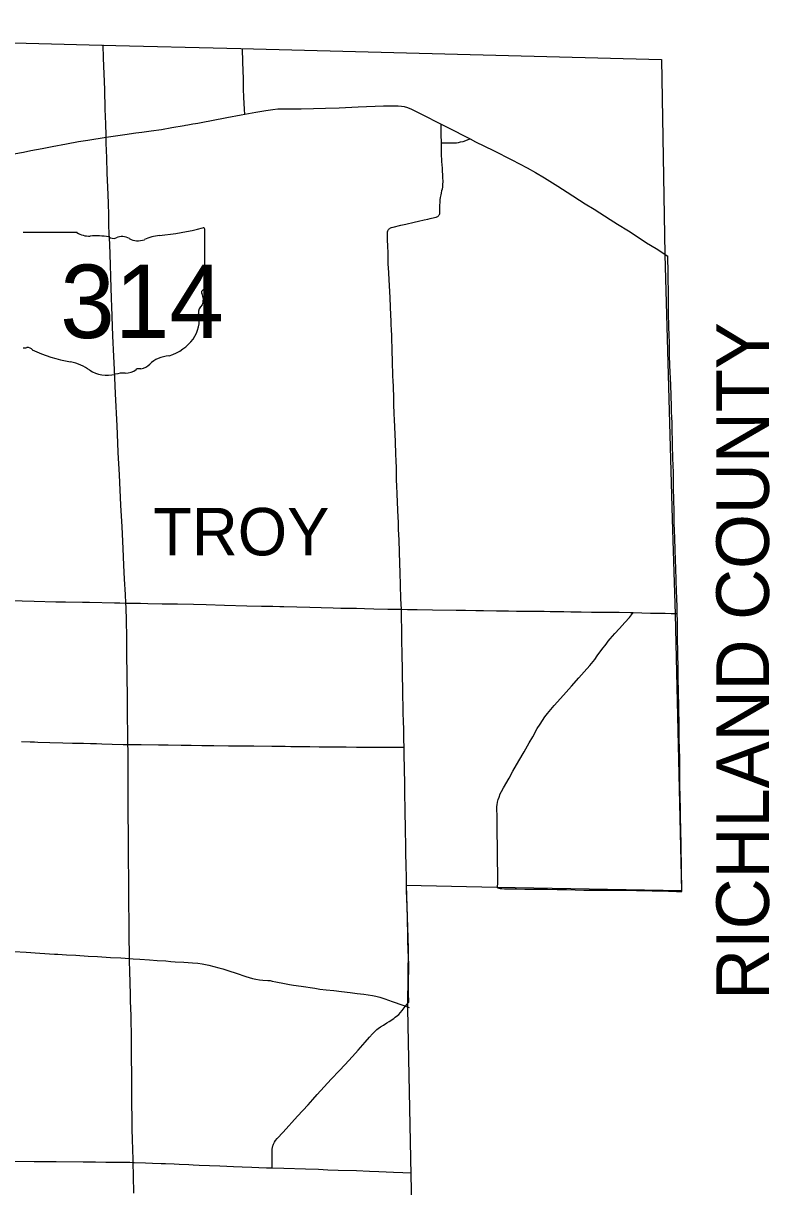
# Model space of a CAD drawing. Extents: x 9078 to 9739, y 4248 to 4966.
# Drawn here: x 9605 to 9675.8, y 4827.9 to 4938.2 of the extents above; entities that cross this region are included whole.
import ezdxf

# ---------------------------------------------------------------- set-up
doc = ezdxf.new("R2010")
doc.units = 0
for name, color, linetype in [('GM_X_Adjacent_County_Text', 7, 'Continuous'), ('GM_X_County', 7, 'Continuous'), ('GM_X_County_Road', 7, 'Continuous'), ('GM_X_State_Route', 7, 'Continuous'), ('GM_X_State_Shield', 7, 'Continuous'), ('GM_X_Township_Road', 7, 'Continuous'), ('GM_X_Township_Text', 7, 'Continuous')]:
    doc.layers.add(name, color=color, linetype=linetype)

msp = doc.modelspace()

# ---------------------------------------------------------------- linework, layer by layer
at = {"layer": 'GM_X_County'}
msp.add_lwpolyline([(9527.58, 4938.18), (9534.01, 4938.03), (9544.57, 4937.79), (9580.15, 4937.8), (9580.15, 4936.95), (9612.46, 4936.11), (9625.64, 4935.77), (9665.53, 4934.74), (9665.86, 4916.26), (9666.54, 4891.17), (9666.82, 4882.14), (9667.42, 4855.9), (9649.93, 4856.23), (9641.33, 4856.41), (9641.51, 4850.43), (9641.44, 4845.14), (9641.45, 4844.73), (9641.78, 4828.99), (9642.12, 4813.07)], dxfattribs=at)
at = {"layer": 'GM_X_County_Road'}
for points in [[(9597.99, 4883.64), (9598.12, 4883.64), (9598.92, 4883.61), (9599.5, 4883.58), (9600.48, 4883.55), (9602.12, 4883.51), (9603.43, 4883.47), (9604.91, 4883.42), (9606.05, 4883.39), (9608.1, 4883.33), (9609.01, 4883.31), (9610.64, 4883.29), (9611.3, 4883.28), (9613.67, 4883.22), (9614.16, 4883.21), (9614.73, 4883.2)], [(9614.73, 4883.2), (9615.49, 4883.18), (9616.13, 4883.18), (9616.82, 4883.17), (9618.18, 4883.14), (9619.65, 4883.12), (9621.14, 4883.09), (9622.36, 4883.05), (9624.08, 4883.01), (9626.21, 4882.94), (9627.6, 4882.91), (9628.67, 4882.89), (9629.33, 4882.87), (9629.73, 4882.86), (9630.96, 4882.83), (9632.19, 4882.8), (9633.26, 4882.77), (9634.41, 4882.75), (9635.14, 4882.73), (9635.88, 4882.72), (9636.62, 4882.7), (9637.36, 4882.68), (9638.26, 4882.66), (9639.57, 4882.63), (9640.8, 4882.61), (9640.87, 4882.61)], [(9640.87, 4882.61), (9641.45, 4882.59), (9642.36, 4882.58), (9643.83, 4882.56), (9646.05, 4882.53), (9646.95, 4882.52), (9647.93, 4882.5), (9648.67, 4882.49), (9649.9, 4882.47), (9651.04, 4882.45), (9651.78, 4882.44), (9652.76, 4882.43), (9653.17, 4882.43), (9653.58, 4882.43), (9654.4, 4882.42), (9654.97, 4882.41), (9655.63, 4882.41), (9656.28, 4882.39), (9656.94, 4882.38), (9657.92, 4882.37), (9658.91, 4882.35), (9659.48, 4882.34), (9660.55, 4882.34), (9661.53, 4882.32), (9662.6, 4882.29), (9662.86, 4882.29)], [(9662.86, 4882.29), (9663.67, 4882.26), (9664.48, 4882.25), (9665.22, 4882.24), (9665.88, 4882.23), (9666.45, 4882.22), (9666.94, 4882.22), (9667.03, 4882.21)], [(9604.84, 4870.07), (9605.66, 4870.04), (9606.07, 4870.03), (9606.39, 4870.02), (9607.54, 4869.98), (9608.77, 4869.95), (9609.67, 4869.92), (9610.73, 4869.9), (9611.39, 4869.88), (9611.96, 4869.87), (9612.45, 4869.85), (9613.44, 4869.82), (9614.49, 4869.79), (9614.94, 4869.79)], [(9603.54, 4830.29), (9606.03, 4830.26), (9608.14, 4830.25), (9610.7, 4830.22), (9611.85, 4830.2), (9612.84, 4830.19), (9613.66, 4830.19), (9614.64, 4830.19), (9615.13, 4830.17), (9615.42, 4830.15)], [(9615.42, 4830.15), (9615.54, 4830.15), (9616.61, 4830.12), (9617.26, 4830.09), (9618.08, 4830.06), (9618.49, 4830.05), (9619.31, 4830.01), (9619.8, 4829.98), (9620.7, 4829.95), (9621.11, 4829.93), (9621.69, 4829.91), (9622.67, 4829.87), (9623.65, 4829.83), (9624.31, 4829.81), (9624.96, 4829.78), (9625.78, 4829.75), (9626.69, 4829.71), (9627.34, 4829.69), (9628.08, 4829.66), (9628.63, 4829.65)], [(9628.63, 4829.65), (9628.65, 4829.65), (9629.72, 4829.62), (9631.77, 4829.56), (9633, 4829.51), (9633.9, 4829.47), (9634.88, 4829.43), (9636.6, 4829.38), (9637.83, 4829.33), (9638.72, 4829.29), (9640.12, 4829.23), (9641.01, 4829.19), (9641.8, 4829.17)]]:
    msp.add_lwpolyline(points, dxfattribs=at)
at = {"layer": 'GM_X_State_Route'}
for points in [[(9615.49, 4827.25), (9615.45, 4828.89), (9615.42, 4830.15), (9615.42, 4830.44), (9615.38, 4832.33), (9615.35, 4833.31), (9615.32, 4836.76), (9615.31, 4837.74), (9615.31, 4838.15), (9615.31, 4838.32), (9615.3, 4838.97), (9615.29, 4839.63), (9615.28, 4840.45), (9615.28, 4841.6), (9615.27, 4842.01), (9615.26, 4842.66), (9615.25, 4843.24), (9615.23, 4844.22), (9615.21, 4844.63), (9615.19, 4845.62), (9615.17, 4846.19), (9615.15, 4847.09), (9615.12, 4848.4), (9615.1, 4849.14), (9615.09, 4849.5), (9615.07, 4850.21), (9615.06, 4851.19), (9615.04, 4852.34), (9615.04, 4852.92), (9615.04, 4853.57), (9615.03, 4854.15), (9615.03, 4855.29), (9615.02, 4855.87), (9615.01, 4856.2), (9615.01, 4856.52), (9615.01, 4857.26), (9615.01, 4857.67), (9615, 4858.24), (9614.99, 4858.9), (9614.98, 4859.64), (9614.99, 4860.13), (9614.99, 4861.11), (9614.97, 4863.33), (9614.97, 4864.07), (9614.97, 4864.89), (9614.97, 4865.63), (9614.96, 4866.28), (9614.96, 4866.94), (9614.96, 4867.6), (9614.96, 4868.17), (9614.95, 4868.66), (9614.95, 4869.32), (9614.94, 4869.73), (9614.94, 4869.79), (9614.93, 4870.55), (9614.92, 4871.37), (9614.91, 4871.94), (9614.9, 4873.26), (9614.88, 4874.4), (9614.86, 4876.13), (9614.85, 4876.87), (9614.83, 4877.85), (9614.82, 4878.67), (9614.82, 4879.41), (9614.82, 4879.98), (9614.79, 4881.54), (9614.76, 4882.77), (9614.73, 4883.2), (9614.7, 4884), (9614.62, 4885.48), (9614.56, 4886.78), (9614.48, 4888.38), (9614.38, 4890.43), (9614.27, 4892.48), (9614.13, 4895.35), (9614.02, 4897.48), (9613.97, 4898.38), (9613.91, 4900.02), (9613.77, 4903.05), (9613.65, 4905.35), (9613.59, 4906.58), (9613.51, 4908.54), (9613.48, 4909.45), (9613.4, 4911.33), (9613.37, 4912.07), (9613.31, 4914.12), (9613.27, 4915.27), (9613.21, 4917.23), (9613.16, 4918.29), (9613.14, 4918.97), (9613.12, 4919.94), (9613.08, 4921.16), (9613.02, 4922.65), (9612.98, 4923.95), (9612.92, 4925.43), (9612.88, 4926.81), (9612.87, 4927.37), (9612.86, 4927.55), (9612.84, 4928.63), (9612.79, 4930.02), (9612.75, 4931.9), (9612.63, 4934.86), (9612.58, 4936.12)], [(9604.13, 4925.81), (9605.02, 4925.96), (9605.74, 4926.1), (9606.79, 4926.3), (9607.76, 4926.48), (9609.12, 4926.74), (9610.25, 4926.96), (9611.14, 4927.1), (9612.87, 4927.37), (9613.09, 4927.41), (9614.63, 4927.63), (9615.68, 4927.78), (9616.25, 4927.85), (9617.15, 4927.97), (9618.12, 4928.12), (9619.09, 4928.3), (9620.27, 4928.49), (9620.41, 4928.51), (9620.62, 4928.55), (9621.1, 4928.63), (9621.34, 4928.68), (9621.57, 4928.72), (9622.05, 4928.81), (9622.86, 4928.97), (9624.31, 4929.23), (9625.68, 4929.5), (9626.02, 4929.56), (9627.05, 4929.75), (9628.02, 4929.92), (9628.67, 4930.01), (9629.16, 4930.05), (9629.65, 4930.07), (9631.38, 4930.06), (9632.52, 4930.09), (9633.67, 4930.13), (9634.98, 4930.17), (9636.78, 4930.24), (9639.16, 4930.34), (9639.98, 4930.36), (9640.56, 4930.36), (9640.89, 4930.33), (9641.13, 4930.28), (9641.45, 4930.19), (9641.83, 4930.03), (9642.78, 4929.56), (9644.65, 4928.6), (9645.7, 4928.07), (9646.87, 4927.47), (9647.4, 4927.21), (9647.9, 4926.95), (9649.59, 4926.11), (9651.34, 4925.22), (9652.8, 4924.47), (9653.59, 4924.03), (9654.44, 4923.53), (9655.69, 4922.74), (9656.59, 4922.17), (9658.31, 4921.07), (9659.14, 4920.54), (9660.67, 4919.58), (9661.36, 4919.14), (9662.4, 4918.48), (9663.43, 4917.82), (9664.12, 4917.37), (9665.03, 4916.81), (9666.15, 4916.09)]]:
    msp.add_lwpolyline(points, dxfattribs=at)
at = {"layer": 'GM_X_State_Shield'}
for p, q in [((9610.11, 4918.34), (9605.01, 4918.34)), ((9622.24, 4913.07), (9622.24, 4918.6)), ((9622.24, 4913.07), (9622.24, 4913.07))]:
    msp.add_line(p, q, dxfattribs=at)
for centre, major_axis, start_param, end_param in [((9611.32, 4919.56), (1.96, 0), 4.042523, 4.731795), ((9616.04, 4932.74), (18.45, 0), 4.814394, 5.042369), ((9622.05, 4918.62), (0.194, 0), 6.141152, 7.989035), ((9611.97, 4912.4), (7.02, 0), 1.404758, 1.657858), ((9613.56, 4918.23), (0.564, 0), 3.836095, 5.185415), ((9614.39, 4917.01), (1.17, 0), 0.950623, 2.079405), ((9615.9, 4918.68), (1.41, 0), 4.081561, 5.145723), ((9618.4, 4915.11), (3.71, 0), 1.699011, 2.107814), ((9622.2, 4912.66), (0.3, 0), 1.883978, 3.671073), ((9622.03, 4913.05), (0.207, 0), 5.05454, 6.418171), ((9620.29, 4911.97), (1.8, 0), 5.934695, 6.695948), ((9617.08, 4910.05), (4.62, 0), 5.101752, 6.440018), ((9622.94, 4910.76), (1.31, 0), 2.387724, 3.262537), ((9605.07, 4908.64), (1.55, 0), 4.665946, 4.897461), ((9605.39, 4906.98), (0.56, 0), 0.519207, 1.627899), ((9612.45, 4916.47), (13.33, 0), 4.195997, 4.488961), ((9619.02, 4904.62), (2.53, 0), 1.647645, 2.488434), ((9608.48, 4902.84), (4.17, 0), 0.823519, 1.323587), ((9612.99, 4906.92), (2.65, 0), 4.026481, 4.996735), ((9614.71, 4906.13), (1.41, 0), 4.691044, 5.507374), ((9615.99, 4905.11), (0.397, 0), 1.147584, 2.315152), ((9615.82, 4906.56), (1.49, 0), 4.937069, 5.64225), ((9614.52, 4903.27), (2.17, 0), 1.495662, 1.94098)]:
    msp.add_ellipse(centre, major_axis=major_axis, ratio=0.8, start_param=start_param, end_param=end_param, dxfattribs=at)
at = {"layer": 'GM_X_Township_Road'}
for points in [[(9626.02, 4929.56), (9625.99, 4930), (9625.93, 4931.18), (9625.91, 4931.93), (9625.88, 4932.92), (9625.84, 4934.48), (9625.8, 4935.78)], [(9644.66, 4926.84), (9644.64, 4927.62), (9644.65, 4928.51), (9644.65, 4928.6)], [(9644.66, 4926.84), (9645.09, 4926.83), (9645.36, 4926.83), (9645.6, 4926.83), (9645.85, 4926.84), (9646.09, 4926.85), (9646.27, 4926.87), (9646.49, 4926.92), (9646.73, 4926.98), (9647.31, 4927.18), (9647.4, 4927.21)], [(9639.62, 4915.94), (9639.61, 4916.19), (9639.61, 4916.53), (9639.59, 4916.92), (9639.58, 4917.18), (9639.56, 4917.5), (9639.55, 4917.75), (9639.54, 4917.99), (9639.54, 4918.15), (9639.54, 4918.23), (9639.55, 4918.32), (9639.56, 4918.39), (9639.58, 4918.48), (9639.61, 4918.56), (9639.66, 4918.62), (9639.72, 4918.68), (9639.78, 4918.73), (9639.85, 4918.77), (9639.93, 4918.8), (9640.09, 4918.85), (9640.81, 4919.02), (9641.29, 4919.14), (9642.08, 4919.32), (9642.48, 4919.42), (9643.04, 4919.54), (9643.37, 4919.61), (9643.61, 4919.67), (9644.01, 4919.75), (9644.17, 4919.79), (9644.24, 4919.82), (9644.31, 4919.86), (9644.38, 4919.91), (9644.43, 4919.97), (9644.48, 4920.04), (9644.51, 4920.11), (9644.53, 4920.19), (9644.53, 4920.27), (9644.53, 4920.52), (9644.53, 4920.93), (9644.54, 4921.18), (9644.55, 4921.42), (9644.58, 4921.67), (9644.63, 4921.91), (9644.66, 4922.07), (9644.72, 4922.31), (9644.76, 4922.47), (9644.79, 4922.63), (9644.81, 4922.87), (9644.82, 4923.2), (9644.81, 4923.53), (9644.76, 4924.43), (9644.72, 4925.08), (9644.68, 4925.82), (9644.67, 4926.07), (9644.66, 4926.84)], [(9640.42, 4894.82), (9640.4, 4895.53), (9640.39, 4895.98), (9640.37, 4896.72), (9640.35, 4897.29), (9640.3, 4898.52), (9640.22, 4900.57), (9640.19, 4901.15), (9640.16, 4902.05), (9640.16, 4902.29), (9640.15, 4902.53), (9640.14, 4902.69), (9640.11, 4903.67), (9640.08, 4904.33), (9640.07, 4904.66), (9640.05, 4905.15), (9640.03, 4905.72), (9640.02, 4906.13), (9639.99, 4907.12), (9639.95, 4908.43), (9639.92, 4909.25), (9639.91, 4909.49), (9639.89, 4909.9), (9639.84, 4911.21), (9639.8, 4912.2), (9639.77, 4912.69), (9639.74, 4913.34), (9639.72, 4913.83), (9639.67, 4914.56), (9639.66, 4914.97), (9639.63, 4915.37), (9639.62, 4915.87), (9639.62, 4915.94)], [(9666.74, 4891.31), (9666.73, 4891.43), (9666.73, 4891.92), (9666.72, 4892.98), (9666.68, 4894.13), (9666.67, 4894.63), (9666.66, 4895.53), (9666.63, 4896.34), (9666.61, 4896.83), (9666.6, 4897.32), (9666.58, 4897.81), (9666.57, 4898.22), (9666.57, 4898.79), (9666.56, 4899.37), (9666.55, 4899.94), (9666.54, 4900.19), (9666.51, 4900.93), (9666.5, 4901.25), (9666.49, 4901.5), (9666.47, 4901.83), (9666.44, 4902.89), (9666.41, 4903.87), (9666.39, 4904.53), (9666.37, 4905.1), (9666.34, 4905.76), (9666.31, 4906.66), (9666.29, 4907.23), (9666.28, 4907.8), (9666.25, 4908.71), (9666.23, 4909.29), (9666.22, 4909.77), (9666.21, 4910.34), (9666.2, 4911.08), (9666.2, 4912.38), (9666.19, 4912.95), (9666.18, 4913.73), (9666.17, 4914.47), (9666.15, 4916.09)], [(9640.87, 4882.61), (9640.83, 4883.61), (9640.79, 4884.92), (9640.74, 4886.07), (9640.72, 4886.97), (9640.69, 4888.03), (9640.65, 4889.18), (9640.61, 4890.16), (9640.58, 4890.9), (9640.56, 4891.31), (9640.54, 4892.05), (9640.47, 4893.52), (9640.44, 4894.34), (9640.42, 4894.82)], [(9667.03, 4882.21), (9667.03, 4882.42), (9667.01, 4883.07), (9667, 4883.4), (9666.99, 4883.73), (9666.97, 4884.3), (9666.94, 4885.44), (9666.9, 4886.43), (9666.87, 4887.33), (9666.83, 4888.23), (9666.79, 4889.38), (9666.75, 4890.77), (9666.74, 4891.31)], [(9641.13, 4869.52), (9641.11, 4870.25), (9641.11, 4871.07), (9641.07, 4872.13), (9641.05, 4872.62), (9641.04, 4873.28), (9641.02, 4874.51), (9640.98, 4876.88), (9640.95, 4878.36), (9640.92, 4879.67), (9640.91, 4880.25), (9640.9, 4880.98), (9640.89, 4881.56), (9640.88, 4882.46), (9640.87, 4882.61)], [(9649.97, 4856.19), (9649.98, 4856.33), (9650, 4856.62), (9650.01, 4857.03), (9650.01, 4857.69), (9649.99, 4858.67), (9649.98, 4859.41), (9649.97, 4860.39), (9649.96, 4861.13), (9649.94, 4862.03), (9649.94, 4863.02), (9649.93, 4863.67), (9649.93, 4863.92), (9649.95, 4864.08), (9649.99, 4864.32), (9650.05, 4864.56), (9650.13, 4864.8), (9650.25, 4865.1), (9650.36, 4865.32), (9650.55, 4865.67), (9651.08, 4866.61), (9651.44, 4867.25), (9652.02, 4868.24), (9652.51, 4869.09), (9652.99, 4869.95), (9653.32, 4870.52), (9653.76, 4871.31), (9654.02, 4871.73), (9654.24, 4872.07), (9654.48, 4872.4), (9654.74, 4872.72), (9655.37, 4873.48), (9656.23, 4874.47), (9657, 4875.32), (9657.71, 4876.12), (9658.2, 4876.67), (9658.73, 4877.29), (9659.2, 4877.86), (9659.45, 4878.18), (9659.89, 4878.78), (9660.28, 4879.3), (9660.48, 4879.57), (9660.68, 4879.82), (9661.12, 4880.31), (9661.56, 4880.79), (9662.05, 4881.34), (9662.49, 4881.83), (9662.7, 4882.09), (9662.86, 4882.29)], [(9667.47, 4855.85), (9667.46, 4856.02), (9667.42, 4857.88), (9667.39, 4860.34), (9667.34, 4862.97), (9667.33, 4863.79), (9667.31, 4864.69), (9667.29, 4866.09), (9667.28, 4866.74), (9667.27, 4867.65), (9667.26, 4868.63), (9667.24, 4869.21), (9667.22, 4870.44), (9667.2, 4871.58), (9667.18, 4873.31), (9667.15, 4874.87), (9667.13, 4876.02), (9667.12, 4876.67), (9667.11, 4877.41), (9667.1, 4878.07), (9667.06, 4880.36), (9667.05, 4881.51), (9667.03, 4882.17), (9667.03, 4882.21)], [(9614.94, 4869.79), (9616.18, 4869.78), (9617.84, 4869.76), (9618.76, 4869.76), (9619.97, 4869.73), (9620.94, 4869.71), (9621.93, 4869.7), (9623.08, 4869.68), (9624.48, 4869.66), (9625.46, 4869.66), (9625.87, 4869.66), (9626.86, 4869.65), (9628.57, 4869.63), (9629.84, 4869.62), (9630.38, 4869.61), (9631.11, 4869.6), (9632.18, 4869.59), (9633.08, 4869.58), (9634.15, 4869.57), (9635.63, 4869.57), (9636.61, 4869.55), (9638.82, 4869.54), (9640.31, 4869.53), (9640.95, 4869.52), (9641.13, 4869.52)], [(9641.36, 4856.15), (9641.34, 4857.52), (9641.33, 4857.96), (9641.31, 4858.7), (9641.3, 4859.1), (9641.29, 4859.59), (9641.28, 4860.66), (9641.27, 4861.23), (9641.25, 4861.97), (9641.23, 4863.28), (9641.22, 4863.93), (9641.2, 4864.84), (9641.19, 4865.41), (9641.18, 4866.15), (9641.16, 4867.38), (9641.14, 4868.94), (9641.13, 4869.52)], [(9641.41, 4854.62), (9641.4, 4854.93), (9641.36, 4856.15)], [(9649.97, 4856.19), (9650.11, 4856.16), (9650.24, 4856.14), (9650.4, 4856.12), (9650.64, 4856.11), (9651.22, 4856.09), (9651.79, 4856.09), (9652.58, 4856.08), (9653.76, 4856.07), (9654.73, 4856.06), (9655.65, 4856.05), (9656.54, 4856.03), (9657.36, 4856.01), (9658.18, 4855.99), (9659.16, 4855.97), (9659.82, 4855.96), (9660.48, 4855.96), (9661.29, 4855.97), (9662.03, 4855.97), (9662.69, 4855.96), (9663.18, 4855.95), (9663.75, 4855.93), (9664.65, 4855.91), (9664.98, 4855.9), (9666.21, 4855.87), (9666.95, 4855.85), (9667.26, 4855.85), (9667.47, 4855.85)], [(9641.47, 4852.07), (9641.46, 4852.87), (9641.45, 4853.44), (9641.42, 4854.26), (9641.41, 4854.62)], [(9641.52, 4850.27), (9641.51, 4850.5), (9641.49, 4850.99), (9641.48, 4851.56), (9641.47, 4852.07)], [(9604.12, 4850.16), (9605.27, 4850.09), (9606.58, 4850.01), (9607.97, 4849.91), (9608.29, 4849.9), (9609.11, 4849.85), (9610.01, 4849.8), (9611.16, 4849.73), (9612.06, 4849.68), (9613.29, 4849.6), (9614.27, 4849.55), (9614.68, 4849.53), (9615.09, 4849.5)], [(9641.56, 4845.34), (9641.55, 4846.24), (9641.55, 4847.15), (9641.55, 4847.64), (9641.56, 4848.29), (9641.56, 4848.54), (9641.56, 4848.95), (9641.55, 4849.6), (9641.52, 4850.27)], [(9615.09, 4849.5), (9615.42, 4849.47), (9616.07, 4849.43), (9616.97, 4849.36), (9617.71, 4849.31), (9618.53, 4849.26), (9619.02, 4849.22), (9619.43, 4849.19), (9620.24, 4849.14), (9621.06, 4849.09), (9621.57, 4849.04), (9621.97, 4848.99), (9622.29, 4848.94), (9622.6, 4848.87), (9623.07, 4848.75), (9623.56, 4848.61), (9623.95, 4848.5), (9624.5, 4848.33), (9625.2, 4848.09), (9626.13, 4847.78), (9626.44, 4847.68), (9626.76, 4847.6), (9627.08, 4847.53), (9627.4, 4847.47), (9627.73, 4847.44), (9628.21, 4847.41), (9628.42, 4847.4), (9628.6, 4847.36), (9628.95, 4847.29), (9629.77, 4847.13), (9630.25, 4847.04), (9630.64, 4846.97), (9631.37, 4846.86), (9632.67, 4846.67), (9633.15, 4846.6), (9633.72, 4846.53), (9634.46, 4846.45), (9635.19, 4846.37), (9636.01, 4846.27), (9636.66, 4846.19), (9637.31, 4846.12), (9637.71, 4846.06), (9638.12, 4845.99), (9638.44, 4845.92), (9638.84, 4845.82), (9639.3, 4845.66), (9639.99, 4845.42), (9641, 4845.06), (9641.27, 4844.96)], [(9628.63, 4829.65), (9628.62, 4829.85), (9628.62, 4830.42), (9628.6, 4830.99), (9628.6, 4831.24), (9628.61, 4831.4), (9628.64, 4831.56), (9628.67, 4831.72), (9628.7, 4831.8), (9628.73, 4831.88), (9628.76, 4831.95), (9628.84, 4832.09), (9628.94, 4832.23), (9629.1, 4832.42), (9629.65, 4833.02), (9631.03, 4834.53), (9632.02, 4835.63), (9632.46, 4836.11), (9632.89, 4836.6), (9633.56, 4837.32), (9634.22, 4838.04), (9635, 4838.89), (9635.5, 4839.42), (9636.23, 4840.2), (9636.77, 4840.81), (9637.42, 4841.55), (9637.85, 4842.04), (9638.12, 4842.35), (9638.41, 4842.64), (9638.53, 4842.75), (9638.66, 4842.85), (9638.88, 4843), (9639.16, 4843.18), (9639.49, 4843.38), (9639.71, 4843.51), (9640.16, 4843.82), (9640.29, 4843.92), (9640.51, 4844.1), (9640.62, 4844.2), (9640.77, 4844.37), (9640.93, 4844.55), (9641.03, 4844.68), (9641.24, 4844.93), (9641.27, 4844.96)], [(9641.27, 4844.96), (9641.43, 4845.16), (9641.56, 4845.34)], [(9641.27, 4844.96), (9641.43, 4844.92), (9641.61, 4844.84)]]:
    msp.add_lwpolyline(points, dxfattribs=at)

# ---------------------------------------------------------------- texts
at = {"layer": 'GM_X_Adjacent_County_Text'}
msp.add_text('RICHLAND COUNTY', height=5, rotation=90, dxfattribs=at).set_placement((9675.73, 4845.57))
at = {"layer": 'GM_X_State_Shield'}
msp.add_text('314', height=6.961, dxfattribs=at).set_placement((9608.51, 4908.33))
at = {"layer": 'GM_X_Township_Text'}
msp.add_text('TROY', height=4.5, rotation=0, dxfattribs=at).set_placement((9617.33, 4887.72))

doc.saveas('drawing.dxf')
